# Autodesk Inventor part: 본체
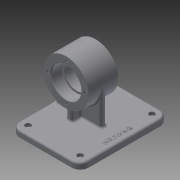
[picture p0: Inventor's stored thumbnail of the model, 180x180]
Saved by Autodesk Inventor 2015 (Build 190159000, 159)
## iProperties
Created: 2019-09
Part Number: 본체
Material: 일반
Document SubType Name: Modeling
Designer: now
Density: 1 g/cm^3
Appearance: 기본값
Author: now
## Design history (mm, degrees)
sketch "스케치1"
  geometry: C1 r 32 at (0, 0); 1 further point
  constraints: 1 centre point, 1 coincident
  dimensions: "d0" = 64 diameter of C1
extrude "돌출1" new body sketch "스케치1" stored distance "d1" = 42; taper "d2" = 0 deg
sketch "스케치2"
  geometry: L1 (32, 0)-(-32, 0); L2 (-32, 0)-(-32, -59); L3 (-32, -59)-(32, -59); L4 (32, -59)-(32, 0); 2 further points
  constraints: 8 end point, 2 parallel, 1 horizontal, 1 horizontal alignment, 1 midpoint, 1 perpendicular, 1 other
  dimensions: "d3" = 64 distance of L1.start L1.end; "d4" = 59 distance of L1.end L2.end
extrude "돌출2" join sketch "스케치2" stored distance "d5" = 8; taper "d6" = 0 deg
sketch "스케치3"
  geometry: L1 (-21, -32)-(-21, 32) reference; L2 (-21, 32)-(21, 32) reference; L3 (21, 32)-(21, -32) reference; L4 (21, -32)-(4, -32) reference; L5 (4, -32)-(4, -59) reference; L6 (4, -59)-(-4, -59) reference; L7 (-4, -59)-(-4, -32) reference; L8 (-4, -32)-(-21, -32) reference; L9 (-17, 0)-(17, 0); L10 (17, 0)-(17, -59); L11 (17, -59)-(-17, -59); L12 (-17, -59)-(-17, 0); 2 further points
  constraints: 8 end point, 2 parallel, 1 coincident, 1 horizontal, 1 midpoint, 1 perpendicular
  dimensions: "d7" = 59 distance of L9.end L10.end; "d8" = 34 distance of L9.start L9.end
extrude "돌출3" join sketch "스케치3" stored distance "d9" = 8; taper "d10" = 0 deg
sketch "스케치4"
  geometry: C1 r 32 at (0, 0) reference; C2 r 21 at (0, 0)
  constraints: 1 centre point, 1 coincident
  dimensions: "d11" = 42 diameter of C2
extrude "돌출4" cut sketch "스케치4" distance "d12" = 15; taper "d13" = 0 deg
sketch "스케치5"
  geometry: C1 r 21 at (0, 0) reference; C2 r 18 at (0, 0)
  constraints: 1 centre point, 1 coincident
  dimensions: "d14" = 36 diameter of C2
extrude "돌출5" cut sketch "스케치5" stored distance "d15" = 15; taper "d16" = 0 deg
node "작업 평면1"
sketch "스케치6"
  geometry: L1 (62, -63)-(-36, -63); L2 (-36, -63)-(-36, 63); L3 (-36, 63)-(62, 63); L4 (62, 63)-(62, -63); 1 further point
  constraints: 8 end point, 2 parallel, 1 horizontal, 1 perpendicular
  dimensions: "d18" = 62 distance from line of point (0, 0) L4; "d19" = 98 distance between parallel lines of L2 L4; "d20" = 126 distance of L3.end L1.start; "d21" = 63 distance from line of point (0, 0) L3
extrude "돌출6" join sketch "스케치6" distance "d22" = 9; taper "d23" = 0 deg
sketch "스케치7"
  geometry: C1 r 21 at (0, 0) reference; 1 further point
  constraints: 1 vertical alignment
  dimensions: "d24" = 26 distance of C1.centre point (0, -26)
hole "구멍1" sketch "스케치7" at (0, -26) diameter "d25" = 3.242; stored, may be unused: countersink angle "d29" = 90 deg, drill point angle "d31" = 118 deg; dims "d26" = 8, "d27" = 4, "d28" = 2, "d30" = 10
fillet "모깎기1" dims "d35" = 12
sketch "스케치8"
  geometry: A1 r 12 centre (50, -51) between (50, -63) and (62, -51) reference; A2 r 12 centre (50, 51) between (62, 51) and (50, 63) reference; A3 r 12 centre (-24, 51) between (-24, 63) and (-36, 51) reference; A4 r 12 centre (-24, -51) between (-36, -51) and (-24, -63) reference; 1 further point
hole "구멍2" sketch "스케치8" at (50, -51), (50, 51), (-24, -51), (-24, 51) diameter "d36" = 4.5; stored, may be unused: countersink angle "d40" = 90 deg, drill point angle "d42" = 118 deg; dims "d37" = 8, "d38" = 8, "d39" = 4.4, "d41" = 10
chamfer "모따기1" distance "d43" = 1; stored, may be unused: second distance "d44" = 2, angle "d45" = 45 deg
fillet "모깎기2" dims "d46" = 0.3
fillet "모깎기3" dims "d47" = 3
fillet "모깎기4" dims "d48" = 3
fillet "모깎기5" dims "d49" = 3
sketch "스케치9"
  geometry: L1 (62, -51)-(62, 51) reference; L2 (-24, -63)-(50, -63) reference; 2 further points
  constraints: 1 other
  dimensions: "d50" = 10 distance from line of point (52, 0) L1; "d51" = 63 distance from line of point (52, 0) L2
feature "엠보싱1" sketch "스케치9" dims "d1" = 42, "d2" = 0, "d52" = 0.5, "d53" = 0
fillet "모깎기6" dims "d54" = 3
fillet "모깎기7" dims "d55" = 3
node "솔리드1"
mirror "대칭1"
pattern_circular "원형 패턴1" dims angle "d33" = 360 deg
mirror "대칭2"
node "절단 모서리 투영1"
node "절단 모서리 투영2"
other parameters: "d17" = -59
